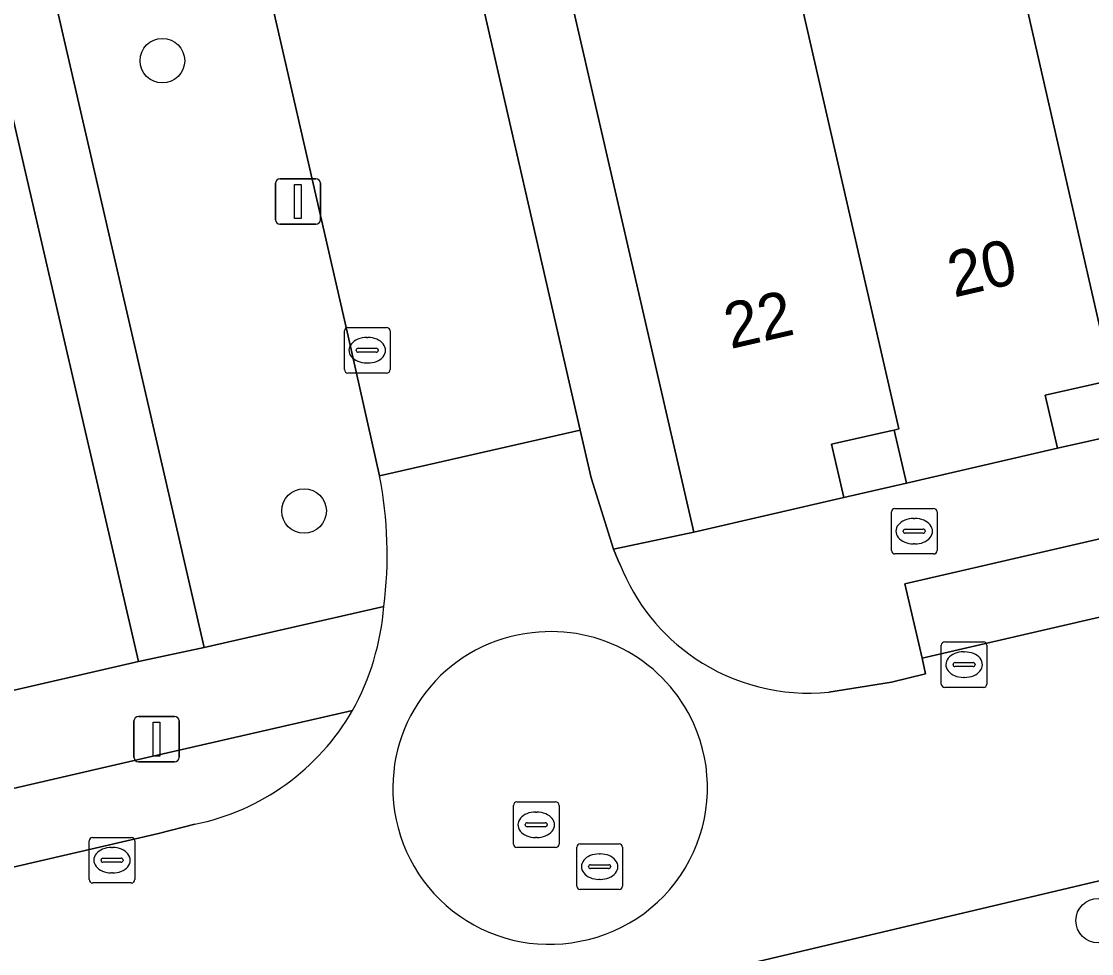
# Model space of a CAD drawing. Extents: x 156412 to 157779, y 382335 to 383768.
# Drawn here: x 157056.03 to 157079.52, y 383030 to 383050.47 of the extents above; entities that cross this region are included whole.
import ezdxf

# ---------------------------------------------------------------- set-up
doc = ezdxf.new("R2010")
doc.units = 0
for name, color, linetype in [('IMGEO_Boom', 7, 'Continuous'), ('IMGEO_Brandkraan', 7, 'Continuous'), ('IMGEO_Erf', 7, 'Continuous'), ('IMGEO_Kolk', 7, 'Continuous'), ('IMGEO_Lichtmast', 7, 'Continuous'), ('IMGEO_Pand', 7, 'Continuous'), ('IMGEO_Pand_nummerreeks', 7, 'Continuous'), ('IMGEO_Parkeervlak_open', 7, 'Continuous'), ('IMGEO_Rijbaan_lokaal_gesloten', 7, 'Continuous'), ('IMGEO_Rijbaan_lokaal_open', 7, 'Continuous'), ('IMGEO_Rioolput', 7, 'Continuous'), ('IMGEO_Voetpad_open', 7, 'Continuous')]:
    doc.layers.add(name, color=color, linetype=linetype)

msp = doc.modelspace()

# ---------------------------------------------------------------- linework, layer by layer
at = {"layer": 'IMGEO_Boom'}
for centre in [(157059.121, 383049.607), (157062.231, 383039.717), (157079.664, 383030.72)]:
    msp.add_circle(centre, 0.489, dxfattribs=at)
at = {"layer": 'IMGEO_Brandkraan'}
for p, q in [((157075.2, 383039.773), (157076.052, 383039.773)), ((157075.125, 383038.847), (157075.125, 383039.699)), ((157075.613, 383039.553), (157075.638, 383039.553)), ((157076.126, 383039.699), (157076.126, 383038.847)), ((157075.427, 383039.316), (157075.825, 383039.316)), ((157075.384, 383039.267), (157075.384, 383039.279)), ((157075.822, 383039.23), (157075.424, 383039.23)), ((157075.868, 383039.279), (157075.868, 383039.267)), ((157075.636, 383038.993), (157075.611, 383038.993)), ((157076.052, 383038.773), (157075.2, 383038.773))]:
    msp.add_line(p, q, dxfattribs=at)
for points in [[(157075.2, 383039.773), (157076.052, 383039.773)], [(157075.125, 383038.847), (157075.125, 383039.699)], [(157076.126, 383039.699), (157076.126, 383038.847)], [(157076.052, 383038.773), (157075.2, 383038.773)]]:
    msp.add_lwpolyline(points, dxfattribs=at)
for centre, radius, start, end in [((157075.202, 383039.697), 0.0765, 91.552, 178.448), ((157075.202, 383039.697), 0.0765, 91.552, 178.448), ((157076.05, 383039.697), 0.0765, 1.552, 88.448), ((157076.05, 383039.697), 0.0765, 1.552, 88.448), ((157075.424, 383039.276), 0.0403, 85.8775, 175.7526), ((157075.829, 383039.278), 0.0386, 1.7309, 96.639), ((157075.421, 383039.266), 0.0366, 178.938, 274.7102), ((157075.825, 383039.273), 0.043, 264.8664, 352.4533), ((157075.202, 383038.849), 0.0765, 181.552, 268.448), ((157075.202, 383038.849), 0.0765, 181.552, 268.448), ((157076.05, 383038.849), 0.0765, 271.552, 358.448), ((157076.05, 383038.849), 0.0765, 271.552, 358.448)]:
    msp.add_arc(centre, radius, start, end, dxfattribs=at)
for centre, major_axis, ratio, start_param, end_param in [((157075.612, 383039.273), (-0.387, 0.002), 0.722429, 4.712389, 7.853982), ((157075.637, 383039.273), (-0.39, 0.002), 0.717154, 1.570796, 4.712389)]:
    msp.add_ellipse(centre, major_axis=major_axis, ratio=ratio, start_param=start_param, end_param=end_param, dxfattribs=at)
at = {"layer": 'IMGEO_Erf'}
for points in [[(157080.146, 383041.405), (157079.874, 383042.574), (157079.764, 383042.549), (157078.5, 383042.263), (157078.772, 383041.094)], [(157075.456, 383040.325), (157075.184, 383041.494), (157075.074, 383041.469), (157073.81, 383041.183), (157074.082, 383040.014)]]:
    msp.add_lwpolyline(points, close=True, dxfattribs=at)
at = {"layer": 'IMGEO_Kolk'}
for p, q in [((157063.117, 383042.821), (157063.117, 383043.673)), ((157063.192, 383043.747), (157064.044, 383043.747)), ((157063.605, 383043.527), (157063.63, 383043.527)), ((157064.118, 383043.673), (157064.118, 383042.821)), ((157063.419, 383043.29), (157063.817, 383043.29)), ((157063.376, 383043.241), (157063.376, 383043.253)), ((157063.814, 383043.204), (157063.416, 383043.204)), ((157063.86, 383043.253), (157063.86, 383043.241)), ((157063.628, 383042.967), (157063.603, 383042.967)), ((157064.044, 383042.747), (157063.192, 383042.747)), ((157076.22, 383035.917), (157076.22, 383036.769)), ((157076.295, 383036.843), (157077.147, 383036.843)), ((157077.221, 383036.769), (157077.221, 383035.917)), ((157076.708, 383036.623), (157076.733, 383036.623)), ((157076.479, 383036.337), (157076.479, 383036.349)), ((157076.917, 383036.3), (157076.519, 383036.3)), ((157076.522, 383036.386), (157076.92, 383036.386)), ((157076.963, 383036.349), (157076.963, 383036.337)), ((157076.731, 383036.063), (157076.706, 383036.063)), ((157077.147, 383035.843), (157076.295, 383035.843)), ((157057.589, 383032.547), (157058.441, 383032.547)), ((157057.514, 383031.621), (157057.514, 383032.473)), ((157058.002, 383032.327), (157058.027, 383032.327)), ((157058.515, 383032.473), (157058.515, 383031.621)), ((157057.773, 383032.041), (157057.773, 383032.053)), ((157057.816, 383032.09), (157058.214, 383032.09)), ((157058.257, 383032.053), (157058.257, 383032.041)), ((157058.211, 383032.004), (157057.813, 383032.004)), ((157058.441, 383031.547), (157057.589, 383031.547)), ((157058.025, 383031.767), (157058, 383031.767))]:
    msp.add_line(p, q, dxfattribs=at)
for points in [[(157063.117, 383042.821), (157063.117, 383043.673)], [(157063.192, 383043.747), (157064.044, 383043.747)], [(157064.118, 383043.673), (157064.118, 383042.821)], [(157064.044, 383042.747), (157063.192, 383042.747)], [(157076.22, 383035.917), (157076.22, 383036.769)], [(157076.295, 383036.843), (157077.147, 383036.843)], [(157077.221, 383036.769), (157077.221, 383035.917)], [(157077.147, 383035.843), (157076.295, 383035.843)], [(157057.589, 383032.547), (157058.441, 383032.547)], [(157057.514, 383031.621), (157057.514, 383032.473)], [(157058.515, 383032.473), (157058.515, 383031.621)], [(157058.441, 383031.547), (157057.589, 383031.547)]]:
    msp.add_lwpolyline(points, dxfattribs=at)
for centre, radius, start, end in [((157063.194, 383043.671), 0.0765, 91.552, 178.448), ((157063.194, 383043.671), 0.0765, 91.552, 178.448), ((157064.042, 383043.671), 0.0765, 1.552, 88.448), ((157064.042, 383043.671), 0.0765, 1.552, 88.448), ((157063.416, 383043.25), 0.0403, 85.8775, 175.7526), ((157063.821, 383043.252), 0.0386, 1.7309, 96.639), ((157063.413, 383043.24), 0.0366, 178.938, 274.7102), ((157063.817, 383043.247), 0.043, 264.8664, 352.4533), ((157063.194, 383042.823), 0.0765, 181.552, 268.448), ((157063.194, 383042.823), 0.0765, 181.552, 268.448), ((157064.042, 383042.823), 0.0765, 271.552, 358.448), ((157064.042, 383042.823), 0.0765, 271.552, 358.448), ((157076.297, 383036.767), 0.0765, 91.552, 178.448), ((157076.297, 383036.767), 0.0765, 91.552, 178.448), ((157077.145, 383036.767), 0.0765, 1.552, 88.448), ((157077.145, 383036.767), 0.0765, 1.552, 88.448), ((157076.519, 383036.346), 0.0403, 85.8775, 175.7526), ((157076.516, 383036.336), 0.0366, 178.938, 274.7102), ((157076.92, 383036.343), 0.043, 264.8664, 352.4533), ((157076.924, 383036.348), 0.0386, 1.7309, 96.639), ((157076.297, 383035.919), 0.0765, 181.552, 268.448), ((157076.297, 383035.919), 0.0765, 181.552, 268.448), ((157077.145, 383035.919), 0.0765, 271.552, 358.448), ((157077.145, 383035.919), 0.0765, 271.552, 358.448), ((157057.591, 383032.471), 0.0765, 91.552, 178.448), ((157057.591, 383032.471), 0.0765, 91.552, 178.448), ((157058.439, 383032.471), 0.0765, 1.552, 88.448), ((157058.439, 383032.471), 0.0765, 1.552, 88.448), ((157057.813, 383032.05), 0.0403, 85.8775, 175.7526), ((157057.81, 383032.04), 0.0366, 178.938, 274.7102), ((157058.214, 383032.047), 0.043, 264.8664, 352.4533), ((157058.218, 383032.052), 0.0386, 1.7309, 96.639), ((157057.591, 383031.623), 0.0765, 181.552, 268.448), ((157057.591, 383031.623), 0.0765, 181.552, 268.448), ((157058.439, 383031.623), 0.0765, 271.552, 358.448), ((157058.439, 383031.623), 0.0765, 271.552, 358.448)]:
    msp.add_arc(centre, radius, start, end, dxfattribs=at)
for centre, major_axis, ratio, start_param, end_param in [((157063.604, 383043.247), (-0.387, 0.002), 0.722429, 4.712389, 7.853982), ((157063.629, 383043.247), (-0.39, 0.002), 0.717154, 1.570796, 4.712389), ((157076.707, 383036.343), (-0.387, 0.002), 0.722429, 4.712389, 7.853982), ((157076.732, 383036.343), (-0.39, 0.002), 0.717154, 1.570796, 4.712389), ((157058.001, 383032.047), (-0.387, 0.002), 0.722429, 4.712389, 7.853982), ((157058.026, 383032.047), (-0.39, 0.002), 0.717154, 1.570796, 4.712389)]:
    msp.add_ellipse(centre, major_axis=major_axis, ratio=ratio, start_param=start_param, end_param=end_param, dxfattribs=at)
at = {"layer": 'IMGEO_Lichtmast'}
for p, q in [((157061.6, 383046.114), (157061.6, 383046.914)), ((157061.6, 383046.914), (157061.6, 383046.114)), ((157061.7, 383047.014), (157062.49, 383047.014)), ((157062.49, 383047.014), (157061.7, 383047.014)), ((157062.59, 383046.914), (157062.59, 383046.114)), ((157062.59, 383046.114), (157062.59, 383046.914)), ((157062.49, 383046.014), (157061.7, 383046.014)), ((157061.7, 383046.014), (157062.49, 383046.014)), ((157058.497, 383034.307), (157058.497, 383035.107)), ((157058.497, 383035.107), (157058.497, 383034.307)), ((157058.597, 383035.207), (157059.387, 383035.207)), ((157059.387, 383035.207), (157058.597, 383035.207)), ((157059.487, 383035.107), (157059.487, 383034.307)), ((157059.487, 383034.307), (157059.487, 383035.107)), ((157059.387, 383034.207), (157058.597, 383034.207)), ((157058.597, 383034.207), (157059.387, 383034.207))]:
    msp.add_line(p, q, dxfattribs=at)
for points in [[(157062.02, 383046.889), (157062.17, 383046.889), (157062.17, 383046.139), (157062.02, 383046.139), (157062.02, 383046.889)], [(157058.917, 383035.082), (157059.067, 383035.082), (157059.067, 383034.332), (157058.917, 383034.332), (157058.917, 383035.082)]]:
    msp.add_lwpolyline(points, dxfattribs=at)
for centre, start, end in [((157061.7, 383046.914), 90, 180), ((157061.7, 383046.914), 90, 180), ((157062.49, 383046.914), 0, 90), ((157062.49, 383046.914), 360, 90), ((157061.7, 383046.114), 180, 270), ((157061.7, 383046.114), 180, 270), ((157062.49, 383046.114), 270, 0), ((157062.49, 383046.114), 270, 0), ((157058.597, 383035.107), 90, 180), ((157058.597, 383035.107), 90, 180), ((157059.387, 383035.107), 0, 90), ((157059.387, 383035.107), 360, 90), ((157058.597, 383034.307), 180, 270), ((157058.597, 383034.307), 180, 270), ((157059.387, 383034.307), 270, 0), ((157059.387, 383034.307), 270, 0)]:
    msp.add_arc(centre, 0.1, start, end, dxfattribs=at)
at = {"layer": 'IMGEO_Pand'}
for points in [[(157081.935, 383055.608), (157077.242, 383054.538), (157079.965, 383042.595), (157079.874, 383042.574), (157080.146, 383041.405), (157083.446, 383042.163), (157083.174, 383043.332), (157084.438, 383043.618), (157084.548, 383043.643), (157084.642, 383043.664)], [(157077.242, 383054.538), (157072.55, 383053.468), (157075.289, 383041.518), (157075.184, 383041.494), (157075.456, 383040.325), (157078.772, 383041.094), (157078.5, 383042.263), (157079.764, 383042.549), (157079.874, 383042.574), (157079.965, 383042.595)], [(157072.55, 383053.468), (157067.762, 383052.377), (157070.787, 383039.253), (157074.082, 383040.014), (157073.81, 383041.183), (157075.074, 383041.469), (157075.184, 383041.494), (157075.289, 383041.518)], [(157055.561, 383049.561), (157050.565, 383048.382), (157053.323, 383036.469), (157053.519, 383036.51), (157053.639, 383036.49), (157055.016, 383036.819), (157055.288, 383035.65), (157058.598, 383036.411)]]:
    msp.add_lwpolyline(points, close=True, dxfattribs=at)
at = {"layer": 'IMGEO_Parkeervlak_open'}
for points in [[(157063.89, 383040.486), (157063.199, 383043.56), (157051.788, 383093.312), (157047.229, 383092.303), (157060.035, 383036.721), (157063.984, 383037.622)], [(157063.292, 383035.332), (157058.884, 383034.325), (157004.064, 383021.641), (157004.317, 383020.493)], [(157006.803, 383020.544), (157007.695, 383020.741), (157059.033, 383032.635), (157059.831, 383032.836)]]:
    msp.add_lwpolyline(points, dxfattribs=at)
for points in [[(157126.734, 383048.265), (157126.347, 383049.879), (157075.416, 383038.117), (157075.802, 383036.486)], [(157130.648, 383041.534), (157130.075, 383043.523), (157068.115, 383028.853), (157007.386, 383014.842), (157007.744, 383013.169), (157069.138, 383027.297)]]:
    msp.add_lwpolyline(points, close=True, dxfattribs=at)
for centre, radius, start, end in [((157054.921, 383038.758), 9.134, 352.8553, 10.9044), ((157058.794, 383037.922), 5.191, 281.5276, 330.0691)]:
    msp.add_arc(centre, radius, start, end, dxfattribs=at)
at = {"layer": 'IMGEO_Rijbaan_lokaal_gesloten'}
msp.add_lwpolyline([(157056.19, 383094.365), (157051.788, 383093.312), (157063.199, 383043.56), (157063.89, 383040.486), (157068.295, 383041.495)], close=True, dxfattribs=at)
for points in [[(157128.107, 383048.559), (157126.734, 383048.265), (157075.802, 383036.486), (157075.875, 383036.143), (157075.126, 383035.957), (157073.753, 383035.739)], [(157007.077, 383015.137), (157007.312, 383015.191), (157007.386, 383014.842), (157068.115, 383028.853), (157130.075, 383043.523)], [(157069.173, 383038.534), (157069.127, 383038.633), (157069.075, 383038.755), (157069.025, 383038.878), (157068.535, 383040.447), (157068.295, 383041.495), (157063.89, 383040.486)], [(157059.831, 383032.836), (157059.033, 383032.635), (157007.695, 383020.741), (157006.803, 383020.544)]]:
    msp.add_lwpolyline(points, dxfattribs=at)
for centre, radius, start, end in [((157054.921, 383038.758), 9.134, 352.8553, 10.9044), ((157073.302, 383040.149), 4.433, 201.3607, 235.85), ((157058.328, 383038.082), 5.675, 331.0185, 355.3536), ((157067.61, 383033.633), 3.43, 96.1621, 182.3834), ((157067.656, 383033.636), 3.432, 24.1802, 96.9341), ((157073.304, 383040.161), 4.444, 235.9095, 275.798), ((157058.794, 383037.922), 5.191, 281.5276, 330.0691), ((157067.657, 383033.639), 3.43, 280.5343, 24.1397), ((157067.611, 383033.632), 3.431, 182.3678, 281.3042)]:
    msp.add_arc(centre, radius, start, end, dxfattribs=at)
at = {"layer": 'IMGEO_Rijbaan_lokaal_open'}
for centre, radius, start, end in [((157067.61, 383033.633), 3.43, 96.1621, 182.3834), ((157067.656, 383033.636), 3.432, 24.1802, 96.9341), ((157067.657, 383033.639), 3.43, 280.5343, 24.1397), ((157067.611, 383033.632), 3.431, 182.3678, 281.3042)]:
    msp.add_arc(centre, radius, start, end, dxfattribs=at)
at = {"layer": 'IMGEO_Rioolput'}
for p, q in [((157066.827, 383032.4), (157066.827, 383033.252)), ((157066.902, 383033.326), (157067.754, 383033.326)), ((157067.828, 383033.252), (157067.828, 383032.4)), ((157067.315, 383033.106), (157067.34, 383033.106)), ((157067.086, 383032.82), (157067.086, 383032.832)), ((157067.524, 383032.783), (157067.126, 383032.783)), ((157067.129, 383032.869), (157067.527, 383032.869)), ((157067.57, 383032.832), (157067.57, 383032.82)), ((157067.338, 383032.546), (157067.313, 383032.546)), ((157067.754, 383032.326), (157066.902, 383032.326)), ((157068.219, 383031.48), (157068.219, 383032.332)), ((157068.294, 383032.406), (157069.146, 383032.406)), ((157069.22, 383032.332), (157069.22, 383031.48)), ((157068.707, 383032.186), (157068.732, 383032.186)), ((157068.478, 383031.9), (157068.478, 383031.912)), ((157068.916, 383031.863), (157068.518, 383031.863)), ((157068.521, 383031.949), (157068.919, 383031.949)), ((157068.962, 383031.912), (157068.962, 383031.9)), ((157068.73, 383031.626), (157068.705, 383031.626)), ((157069.146, 383031.406), (157068.294, 383031.406))]:
    msp.add_line(p, q, dxfattribs=at)
for points in [[(157066.827, 383032.4), (157066.827, 383033.252)], [(157066.902, 383033.326), (157067.754, 383033.326)], [(157067.828, 383033.252), (157067.828, 383032.4)], [(157067.754, 383032.326), (157066.902, 383032.326)], [(157068.219, 383031.48), (157068.219, 383032.332)], [(157068.294, 383032.406), (157069.146, 383032.406)], [(157069.22, 383032.332), (157069.22, 383031.48)], [(157069.146, 383031.406), (157068.294, 383031.406)]]:
    msp.add_lwpolyline(points, dxfattribs=at)
for centre, radius, start, end in [((157066.904, 383033.25), 0.0765, 91.552, 178.448), ((157066.904, 383033.25), 0.0765, 91.552, 178.448), ((157067.752, 383033.25), 0.0765, 1.552, 88.448), ((157067.752, 383033.25), 0.0765, 1.552, 88.448), ((157067.126, 383032.829), 0.0403, 85.8775, 175.7526), ((157067.123, 383032.819), 0.0366, 178.938, 274.7102), ((157067.527, 383032.826), 0.043, 264.8664, 352.4533), ((157067.531, 383032.831), 0.0386, 1.7309, 96.639), ((157066.904, 383032.402), 0.0765, 181.552, 268.448), ((157066.904, 383032.402), 0.0765, 181.552, 268.448), ((157067.752, 383032.402), 0.0765, 271.552, 358.448), ((157067.752, 383032.402), 0.0765, 271.552, 358.448), ((157068.296, 383032.33), 0.0765, 91.552, 178.448), ((157068.296, 383032.33), 0.0765, 91.552, 178.448), ((157069.144, 383032.33), 0.0765, 1.552, 88.448), ((157069.144, 383032.33), 0.0765, 1.552, 88.448), ((157068.518, 383031.909), 0.0403, 85.8775, 175.7526), ((157068.515, 383031.899), 0.0366, 178.938, 274.7102), ((157068.919, 383031.906), 0.043, 264.8664, 352.4533), ((157068.923, 383031.911), 0.0386, 1.7309, 96.639), ((157068.296, 383031.482), 0.0765, 181.552, 268.448), ((157068.296, 383031.482), 0.0765, 181.552, 268.448), ((157069.144, 383031.482), 0.0765, 271.552, 358.448), ((157069.144, 383031.482), 0.0765, 271.552, 358.448)]:
    msp.add_arc(centre, radius, start, end, dxfattribs=at)
for centre, major_axis, ratio, start_param, end_param in [((157067.314, 383032.826), (-0.387, 0.002), 0.722429, 4.712389, 7.853982), ((157067.339, 383032.826), (-0.39, 0.002), 0.717154, 1.570796, 4.712389), ((157068.706, 383031.906), (-0.387, 0.002), 0.722429, 4.712389, 7.853982), ((157068.731, 383031.906), (-0.39, 0.002), 0.717154, 1.570796, 4.712389)]:
    msp.add_ellipse(centre, major_axis=major_axis, ratio=ratio, start_param=start_param, end_param=end_param, dxfattribs=at)
at = {"layer": 'IMGEO_Voetpad_open'}
for points in [[(157061.279, 383080.375), (157060.986, 383081.639), (157057.96, 383094.77), (157056.19, 383094.365), (157068.295, 383041.495), (157068.535, 383040.447), (157069.025, 383038.878), (157070.787, 383039.253), (157067.762, 383052.377), (157067.467, 383053.653)], [(157047.229, 383092.303), (157045.778, 383091.965), (157048.801, 383078.827), (157049.105, 383077.512), (157055.278, 383050.786), (157055.561, 383049.561), (157058.598, 383036.411), (157060.035, 383036.721)]]:
    msp.add_lwpolyline(points, close=True, dxfattribs=at)
for points in [[(157073.753, 383035.739), (157075.126, 383035.957), (157075.875, 383036.143), (157075.802, 383036.486), (157075.416, 383038.117), (157126.347, 383049.879)], [(157080.146, 383041.405), (157078.772, 383041.094), (157075.456, 383040.325), (157074.082, 383040.014), (157070.787, 383039.253), (157069.025, 383038.878), (157069.075, 383038.755), (157069.127, 383038.633), (157069.173, 383038.534)], [(157063.984, 383037.622), (157060.035, 383036.721), (157058.598, 383036.411), (157055.288, 383035.65), (157053.91, 383035.322), (157053.8, 383035.297), (157050.604, 383034.561), (157049.233, 383034.252), (157049.123, 383034.226), (157045.937, 383033.486), (157044.563, 383033.175), (157044.453, 383033.149), (157041.253, 383032.406), (157037.444, 383031.528), (157034.319, 383030.804), (157032.113, 383030.31), (157028.945, 383029.562), (157026.702, 383029.05), (157023.604, 383028.339), (157022.044, 383027.988), (157018.742, 383027.222), (157017.372, 383026.91), (157014.054, 383026.13)], [(157058.884, 383034.325), (157063.292, 383035.332)], [(157004.317, 383020.493), (157004.064, 383021.641), (157058.884, 383034.325)]]:
    msp.add_lwpolyline(points, dxfattribs=at)
for centre, radius, start, end in [((157073.302, 383040.149), 4.433, 201.3607, 235.85), ((157058.328, 383038.082), 5.675, 331.0185, 355.3536), ((157073.304, 383040.161), 4.444, 235.9095, 275.798)]:
    msp.add_arc(centre, radius, start, end, dxfattribs=at)

# ---------------------------------------------------------------- texts
at = {"layer": 'IMGEO_Pand_nummerreeks'}
for s, p in [('20', (157076.497, 383044.402)), ('22', (157071.59, 383043.271))]:
    msp.add_text(s, height=1, rotation=12.9775, dxfattribs=at).set_placement(p)

doc.saveas('drawing.dxf')
